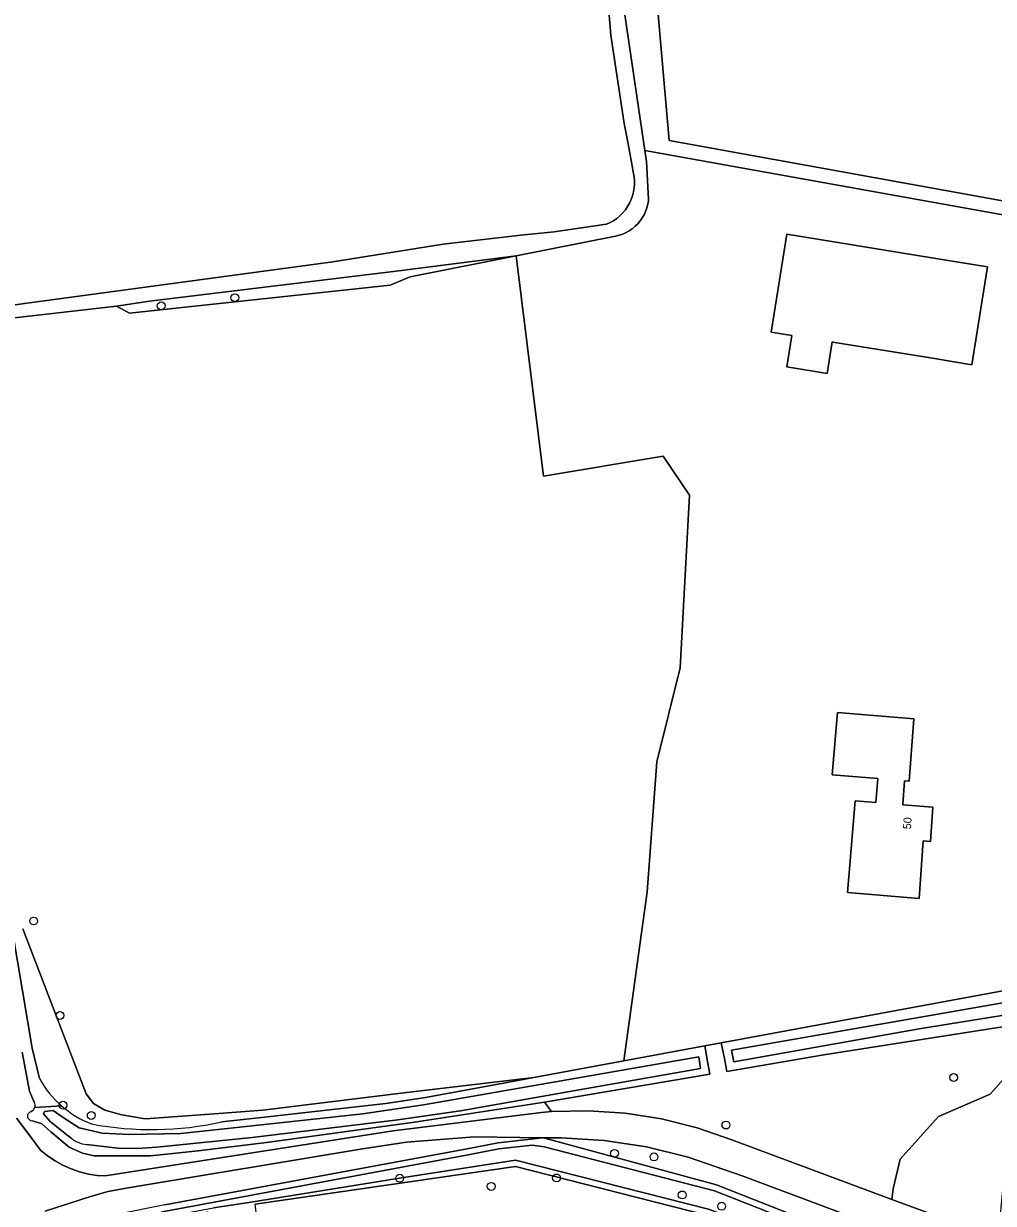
# Model space of a CAD drawing. Extents: x 161385 to 162589, y 388479 to 389756.
# Drawn here: x 162377.3 to 162498.2, y 389100.4 to 389247.5 of the extents above; entities that cross this region are included whole.
import ezdxf

# ---------------------------------------------------------------- set-up
doc = ezdxf.new("R2010")
doc.units = 0
for name, color, linetype in [('IMGEO_Boom', 7, 'Continuous'), ('IMGEO_Bouwland', 7, 'Continuous'), ('IMGEO_Erf', 7, 'Continuous'), ('IMGEO_Grasland_agrarisch', 7, 'Continuous'), ('IMGEO_Grasland_overig', 7, 'Continuous'), ('IMGEO_Groenvoorziening', 7, 'Continuous'), ('IMGEO_Hek', 7, 'Continuous'), ('IMGEO_Loofbos', 7, 'Continuous'), ('IMGEO_Oever', 7, 'Continuous'), ('IMGEO_Pand', 7, 'Continuous'), ('IMGEO_Pand_nummerreeks', 7, 'Continuous'), ('IMGEO_Waterloop', 7, 'Continuous')]:
    doc.layers.add(name, color=color, linetype=linetype)

msp = doc.modelspace()

# ---------------------------------------------------------------- linework, layer by layer
at = {"layer": 'IMGEO_Boom'}
for centre in [(162403.61, 389213.31), (162394.43, 389212.3), (162378.51, 389135.58), (162381.8, 389123.8), (162493.28, 389116.07), (162382.18, 389112.62), (162385.7, 389111.34), (162464.87, 389110.14), (162450.97, 389106.61), (162455.9, 389106.17), (162424.17, 389103.51), (162435.59, 389102.49), (162443.74, 389103.55), (162459.42, 389101.43), (162464.33, 389100.02)]:
    msp.add_circle(centre, 0.489, dxfattribs=at)
at = {"layer": 'IMGEO_Bouwland'}
for points in [[(162365.69, 389304.53), (162378.86, 389305.21), (162381.46, 389305.34), (162386.58, 389305.3), (162392.87, 389304.96), (162400.44, 389304.98), (162407.4, 389305.15), (162413.86, 389305.32), (162420.57, 389304.98), (162428.12, 389304.98), (162438.44, 389304.9), (162451.55, 389304.33), (162457.77, 389232.9), (162518.01, 389222.01), (162519.26, 389228.69), (162519.43, 389229.57), (162522.32, 389244.9), (162523.68, 389251.54), (162528.42, 389274.72), (162532.91, 389298.77), (162450.78, 389315.08), (162458.14, 389368.42)], [(162377.18, 389134.61), (162385.06, 389114.05), (162385.99, 389112.81), (162387.38, 389112.01), (162389.52, 389111.42), (162392.41, 389110.92), (162400.48, 389111.49), (162407.09, 389111.98), (162424.68, 389114.17), (162440.91, 389116.07), (162452.14, 389118.14), (162455.04, 389139.22), (162456.26, 389155.42), (162459.17, 389167.14), (162460.31, 389188.68), (162457.04, 389193.56), (162442.11, 389191.05), (162438.69, 389218.52), (162425.48, 389215.91), (162422.97, 389214.86), (162390.49, 389211.37), (162388.85, 389212.27), (162362.66, 389209.24)]]:
    msp.add_lwpolyline(points, dxfattribs=at)
at = {"layer": 'IMGEO_Erf'}
msp.add_lwpolyline([(162517.7, 389220.36), (162461.43, 389230.46), (162454.75, 389231.66), (162454.95, 389230.31), (162455.21, 389225.57), (162455.19, 389225.4), (162455.11, 389224.95), (162455, 389224.5), (162454.84, 389224.07), (162454.65, 389223.65), (162454.42, 389223.26), (162454.16, 389222.88), (162453.86, 389222.53), (162453.54, 389222.21), (162453.18, 389221.91), (162452.81, 389221.65), (162452.41, 389221.43), (162451.99, 389221.24), (162451.55, 389221.09), (162451.11, 389220.98), (162438.69, 389218.52), (162442.11, 389191.05), (162457.04, 389193.56), (162460.31, 389188.68), (162459.17, 389167.14), (162456.26, 389155.42), (162455.04, 389139.22), (162452.14, 389118.14), (162453.7, 389118.43), (162462.23, 389120), (162464.29, 389120.39), (162501.65, 389127.29)], dxfattribs=at)
for points in [[(162472.45, 389204.69), (162473.08, 389208.61), (162470.53, 389209.03), (162472.48, 389221.22), (162492.58, 389217.94), (162497.51, 389217.14), (162495.55, 389204.94), (162490.62, 389205.75), (162478.19, 389207.78), (162478.14, 389207.79), (162477.51, 389203.86)], [(162488.32, 389160.78), (162487.73, 389153.02), (162487.13, 389153.06), (162486.92, 389150.06), (162490.66, 389149.8), (162490.38, 389145.52), (162489.48, 389145.58), (162488.99, 389138.39), (162480.05, 389139.14), (162481.01, 389150.57), (162483.55, 389150.36), (162483.8, 389153.34), (162478.11, 389153.82), (162478.77, 389161.59)]]:
    msp.add_lwpolyline(points, close=True, dxfattribs=at)
at = {"layer": 'IMGEO_Grasland_agrarisch'}
msp.add_lwpolyline([(162362.6, 389210.46), (162377.38, 389212.6), (162415.85, 389217.78), (162429.58, 389219.97), (162439.3, 389221.11), (162443.45, 389221.54), (162449.96, 389222.46), (162450.41, 389222.67), (162450.85, 389222.91), (162451.26, 389223.2), (162451.64, 389223.51), (162451.99, 389223.87), (162452.32, 389224.25), (162452.6, 389224.66), (162452.85, 389225.09), (162453.06, 389225.54), (162453.23, 389226.01), (162453.35, 389226.49), (162453.43, 389226.99), (162453.47, 389227.48), (162453.46, 389227.98), (162453.43, 389228.33), (162452.66, 389232.48), (162452.19, 389235.01), (162450.51, 389246.03), (162450.17, 389250)], dxfattribs=at)
at = {"layer": 'IMGEO_Grasland_overig'}
for points in [[(162452.04, 389250), (162454.75, 389231.66), (162461.43, 389230.46), (162517.7, 389220.36), (162518.01, 389222.01), (162457.77, 389232.9), (162451.55, 389304.33)], [(162490.55, 389099.01), (162485.57, 389100.86), (162465.62, 389108.29), (162461.29, 389109.79), (162456.83, 389110.91), (162452.3, 389111.62), (162447.72, 389111.92), (162443.13, 389111.82), (162441.87, 389111.71), (162423.37, 389109.41), (162387.43, 389103.79), (162386.45, 389103.86), (162385.34, 389104.03), (162384.25, 389104.3), (162383.18, 389104.67), (162382.16, 389105.13), (162381.18, 389105.68), (162380.25, 389106.32), (162379.38, 389107.03), (162377.83, 389109.08), (162376.36, 389111.02)], [(162379.93, 389099.4), (162385.62, 389101.22), (162387.81, 389101.86), (162390.05, 389102.29), (162419.53, 389107.16), (162425.04, 389108), (162433.5, 389108.66), (162441.99, 389108.56), (162442.1, 389108.53), (162444.3, 389108.54), (162449.66, 389108.22), (162454.96, 389107.42), (162460.17, 389106.15), (162466.9, 389103.82), (162489.43, 389095.36)]]:
    msp.add_lwpolyline(points, dxfattribs=at)
msp.add_lwpolyline([(162388.85, 389212.27), (162390.49, 389211.37), (162422.97, 389214.86), (162425.48, 389215.91), (162438.69, 389218.52), (162424.06, 389216.65), (162392.98, 389212.86)], close=True, dxfattribs=at)
at = {"layer": 'IMGEO_Groenvoorziening'}
for points in [[(162374.73, 389137.87), (162375.91, 389134.01), (162378.33, 389119.74), (162379.25, 389115.94)], [(162401.98, 389110.54), (162406.93, 389111.09), (162422.43, 389112.82), (162427.39, 389113.57), (162437.14, 389115.37), (162440.91, 389116.07), (162424.68, 389114.17), (162407.09, 389111.98), (162400.48, 389111.49), (162392.41, 389110.92), (162389.52, 389111.42), (162387.38, 389112.01), (162385.99, 389112.81), (162385.06, 389114.05), (162377.18, 389134.61)], [(162378.59, 389112.98), (162378, 389114.35), (162377.07, 389119.23)], [(162376.36, 389111.02), (162377.83, 389109.08), (162379.38, 389107.03), (162380.25, 389106.32), (162381.18, 389105.68), (162382.16, 389105.13), (162383.18, 389104.67), (162384.25, 389104.3), (162385.34, 389104.03), (162386.45, 389103.86), (162387.43, 389103.79), (162423.37, 389109.41), (162441.87, 389111.71), (162443.13, 389111.82), (162442.25, 389112.99), (162426.03, 389110.5), (162407.57, 389107.98), (162399.05, 389106.93), (162393.07, 389106.32), (162386.05, 389106.32), (162384.59, 389106.65), (162382.95, 389107.39), (162380.64, 389109.28), (162379.53, 389110.31), (162378.38, 389110.68)], [(162378.18, 389111.78), (162378.38, 389111.94)], [(162394.86, 389100.19), (162432.57, 389107.18), (162436.45, 389107.93), (162441.99, 389108.56), (162433.5, 389108.66), (162425.04, 389108), (162419.53, 389107.16), (162390.05, 389102.29), (162387.81, 389101.86), (162385.62, 389101.22), (162379.93, 389099.4)], [(162493.17, 389094.36), (162491.43, 389094.64), (162490.43, 389095), (162489.43, 389095.36), (162466.9, 389103.82), (162460.17, 389106.15), (162454.96, 389107.42), (162449.66, 389108.22), (162444.3, 389108.54), (162442.1, 389108.53), (162463.7, 389102.69), (162488.78, 389092.79), (162488.17, 389091.37), (162487.43, 389089.65), (162462.45, 389098.91)], [(162462.45, 389098.91), (162438.6, 389104.96), (162406.15, 389100.29)]]:
    msp.add_lwpolyline(points, dxfattribs=at)
msp.add_lwpolyline([(162500.78, 389117.31), (162497.83, 389114.01), (162491.39, 389111.2), (162486.6, 389105.87), (162485.73, 389102.19), (162485.57, 389100.86), (162490.55, 389099.01), (162491.45, 389098.72), (162492.35, 389098.43), (162497.21, 389097.36), (162498.96, 389097.09), (162499.85, 389107.07)], close=True, dxfattribs=at)
for centre, radius, start, end in [((162390.3, 389122.04), 12.63, 208.8776, 228.7985), ((162377.83, 389112.59), 0.857, 343.94, 27.1559), ((162378.31, 389111.24), 0.56, 103.1829, 277.3259), ((162377.84, 389112.6), 0.852, 309.6463, 343.423), ((162390.29, 389122.02), 12.6, 228.7668, 248.7297), ((162393.21, 389150.06), 40.48, 259.3425, 282.5113)]:
    msp.add_arc(centre, radius, start, end, dxfattribs=at)
at = {"layer": 'IMGEO_Hek'}
msp.add_lwpolyline([(162454.75, 389231.66), (162461.43, 389230.46)], dxfattribs=at)
at = {"layer": 'IMGEO_Loofbos'}
msp.add_lwpolyline([(162503.71, 389120.57), (162506.53, 389123.52), (162501.24, 389122.69), (162477.09, 389118.89), (162464.99, 389116.84), (162464.67, 389118.46), (162464.29, 389120.39), (162462.23, 389120), (162462.59, 389118.05), (162462.88, 389116.48), (162442.25, 389112.99), (162443.13, 389111.82), (162447.72, 389111.92), (162452.3, 389111.62), (162456.83, 389110.91), (162461.29, 389109.79), (162465.62, 389108.29), (162485.57, 389100.86), (162485.73, 389102.19), (162486.6, 389105.87), (162491.39, 389111.2), (162497.83, 389114.01), (162500.78, 389117.31)], close=True, dxfattribs=at)
at = {"layer": 'IMGEO_Oever'}
for points in [[(162465.56, 389119.47), (162502.48, 389125.91), (162502.94, 389126.12), (162503.14, 389126.51), (162510.18, 389157.95)], [(162512.05, 389157.52), (162509.73, 389146.76), (162505.11, 389125.18), (162504.78, 389124.79), (162504.18, 389124.6), (162488.97, 389122.14), (162465.85, 389118.02), (162465.56, 389119.47)], [(162501.65, 389127.29), (162464.29, 389120.39), (162464.67, 389118.46), (162464.99, 389116.84), (162477.09, 389118.89), (162501.24, 389122.69)], [(162378.38, 389110.68), (162379.53, 389110.31), (162380.64, 389109.28), (162382.95, 389107.39), (162384.59, 389106.65), (162386.05, 389106.32), (162393.07, 389106.32), (162399.05, 389106.93), (162407.57, 389107.98), (162426.03, 389110.5), (162442.25, 389112.99), (162462.88, 389116.48), (162462.59, 389118.05), (162462.23, 389120), (162453.7, 389118.43), (162452.14, 389118.14), (162440.91, 389116.07), (162437.14, 389115.37), (162427.39, 389113.57), (162422.43, 389112.82), (162406.93, 389111.09), (162401.98, 389110.54)], [(162383.15, 389108.54), (162382.67, 389108.92), (162380.58, 389110.57), (162379.73, 389111.53), (162379.86, 389111.82), (162380.93, 389111.94), (162382.32, 389111), (162384.21, 389109.81), (162387.08, 389109.15), (162390.45, 389108.95), (162396.86, 389109.11), (162405.77, 389110.05), (162419.57, 389111.53), (162427.13, 389112.68), (162461.5, 389118.64)], [(162461.5, 389118.64), (162461.71, 389117.19), (162445.14, 389114.28), (162431.75, 389111.93), (162423.95, 389110.79), (162405.76, 389108.58), (162393.88, 389107.38), (162391.45, 389107.21), (162389, 389107.25), (162385.11, 389107.72)], [(162378.38, 389111.94), (162378.18, 389111.78)], [(162381.99, 389112.54), (162378.65, 389112.35)], [(162438.6, 389104.96), (162462.45, 389098.91), (162487.43, 389089.65), (162488.17, 389091.37), (162488.78, 389092.79), (162463.7, 389102.69), (162442.1, 389108.53), (162441.99, 389108.56), (162436.45, 389107.93), (162432.57, 389107.18), (162394.86, 389100.19), (162377.32, 389096.65)], [(162347.23, 389067.62), (162347.31, 389067.7), (162348.23, 389068.55), (162371.26, 389093.09), (162372.06, 389093.78), (162374.29, 389095.17), (162377.48, 389096), (162394.4, 389099.28), (162395.01, 389099.42), (162432.71, 389106.42), (162436.56, 389107.16), (162440.71, 389107.63), (162442.21, 389107.41), (162463.45, 389101.95), (162486.96, 389092.67)], [(162486.57, 389090.85), (162486.5, 389090.86), (162486.36, 389090.89), (162486.21, 389090.93), (162462.68, 389099.65), (162438.64, 389105.75), (162424.17, 389103.51), (162405.34, 389100.5), (162400.96, 389099.82)], [(162377.32, 389095.08), (162400.22, 389099.31), (162400.4, 389097.17), (162406.4, 389098.19), (162406.15, 389100.29), (162438.6, 389104.96)]]:
    msp.add_lwpolyline(points, dxfattribs=at)
for centre, radius, start, end in [((162378.31, 389111.24), 0.56, 103.1829, 277.3259), ((162377.84, 389112.6), 0.852, 309.6463, 343.423), ((162390.29, 389122.02), 12.6, 228.7668, 248.7297), ((162393.21, 389150.06), 40.48, 259.3425, 282.5113), ((162385.59, 389111.63), 3.94, 231.7417, 263.0227)]:
    msp.add_arc(centre, radius, start, end, dxfattribs=at)
at = {"layer": 'IMGEO_Pand'}
for points in [[(162497.51, 389217.14), (162492.58, 389217.94), (162472.48, 389221.22), (162470.53, 389209.03), (162473.08, 389208.61), (162472.45, 389204.69), (162477.51, 389203.86), (162478.14, 389207.79), (162478.19, 389207.78), (162490.62, 389205.75), (162495.55, 389204.94)], [(162488.99, 389138.39), (162489.48, 389145.58), (162490.38, 389145.52), (162490.66, 389149.8), (162486.92, 389150.06), (162487.13, 389153.06), (162487.73, 389153.02), (162488.32, 389160.78), (162478.77, 389161.59), (162478.11, 389153.82), (162483.8, 389153.34), (162483.55, 389150.36), (162481.01, 389150.57), (162480.05, 389139.14)]]:
    msp.add_lwpolyline(points, close=True, dxfattribs=at)
at = {"layer": 'IMGEO_Waterloop'}
for points in [[(162450.17, 389250), (162450.51, 389246.03), (162452.19, 389235.01), (162452.66, 389232.48), (162453.43, 389228.33), (162453.46, 389227.98), (162453.47, 389227.48), (162453.43, 389226.99), (162453.35, 389226.49), (162453.23, 389226.01), (162453.06, 389225.54), (162452.85, 389225.09), (162452.6, 389224.66), (162452.32, 389224.25), (162451.99, 389223.87), (162451.64, 389223.51), (162451.26, 389223.2), (162450.85, 389222.91), (162450.41, 389222.67), (162449.96, 389222.46), (162443.45, 389221.54), (162439.3, 389221.11), (162429.58, 389219.97), (162415.85, 389217.78), (162377.38, 389212.6), (162362.6, 389210.46)], [(162388.85, 389212.27), (162392.98, 389212.86), (162424.06, 389216.65), (162438.69, 389218.52), (162451.11, 389220.98), (162451.55, 389221.09), (162451.99, 389221.24), (162452.41, 389221.43), (162452.81, 389221.65), (162453.18, 389221.91), (162453.54, 389222.21), (162453.86, 389222.53), (162454.16, 389222.88), (162454.42, 389223.26), (162454.65, 389223.65), (162454.84, 389224.07), (162455, 389224.5), (162455.11, 389224.95), (162455.19, 389225.4), (162455.21, 389225.57), (162454.95, 389230.31), (162454.75, 389231.66), (162452.04, 389250)], [(162362.66, 389209.24), (162388.85, 389212.27)], [(162510.18, 389157.95), (162503.14, 389126.51), (162502.94, 389126.12), (162502.48, 389125.91), (162465.56, 389119.47), (162465.85, 389118.02), (162488.97, 389122.14), (162504.18, 389124.6), (162504.78, 389124.79), (162505.11, 389125.18), (162509.73, 389146.76), (162512.05, 389157.52)], [(162379.25, 389115.94), (162378.33, 389119.74), (162375.91, 389134.01), (162374.73, 389137.87)], [(162377.07, 389119.23), (162378, 389114.35), (162378.59, 389112.98)], [(162461.5, 389118.64), (162427.13, 389112.68), (162419.57, 389111.53), (162405.77, 389110.05), (162396.86, 389109.11), (162390.45, 389108.95), (162387.08, 389109.15), (162384.21, 389109.81), (162382.32, 389111), (162380.93, 389111.94), (162379.86, 389111.82), (162379.73, 389111.53), (162380.58, 389110.57), (162382.67, 389108.92), (162383.15, 389108.54)], [(162385.11, 389107.72), (162389, 389107.25), (162391.45, 389107.21), (162393.88, 389107.38), (162405.76, 389108.58), (162423.95, 389110.79), (162431.75, 389111.93), (162445.14, 389114.28), (162461.71, 389117.19), (162461.5, 389118.64)], [(162378.65, 389112.35), (162381.99, 389112.54)], [(162486.96, 389092.67), (162463.45, 389101.95), (162442.21, 389107.41), (162440.71, 389107.63), (162436.56, 389107.16), (162432.71, 389106.42), (162395.01, 389099.42), (162394.4, 389099.28)], [(162347.36, 389067.36), (162347.46, 389067.42), (162348.02, 389067.71), (162371.93, 389093.03), (162374.41, 389094.5), (162377.59, 389095.39), (162389.59, 389097.71), (162400.96, 389099.82), (162405.34, 389100.5), (162424.17, 389103.51), (162438.64, 389105.75), (162462.68, 389099.65), (162486.21, 389090.93), (162486.36, 389090.89), (162486.5, 389090.86), (162486.57, 389090.85)]]:
    msp.add_lwpolyline(points, dxfattribs=at)
for centre, radius, start, end in [((162390.3, 389122.04), 12.63, 208.8776, 228.7985), ((162377.83, 389112.59), 0.857, 343.94, 27.1559), ((162385.59, 389111.63), 3.94, 231.7417, 263.0227)]:
    msp.add_arc(centre, radius, start, end, dxfattribs=at)

# ---------------------------------------------------------------- texts
at = {"layer": 'IMGEO_Pand_nummerreeks'}
msp.add_text('50', height=1, rotation=86.257, dxfattribs=at).set_placement((162487.95, 389147))

doc.saveas('drawing.dxf')
